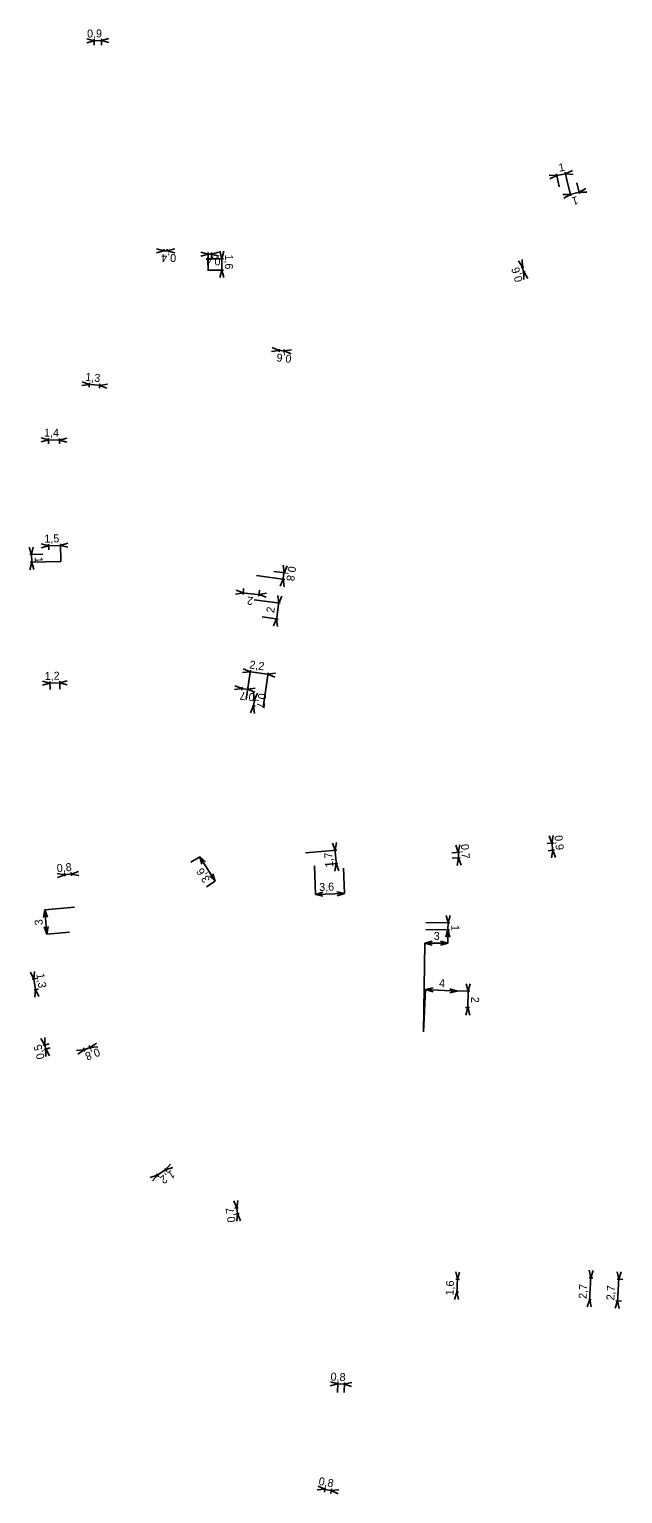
# Model space of a CAD drawing. Extents: x -732085 to -731961, y -1048713 to -1047966.
# Drawn here: x -732046.4 to -731972.2, y -1048148.7 to -1047965.8 of the extents above; entities that cross this region are included whole.
import ezdxf

# ---------------------------------------------------------------- set-up
doc = ezdxf.new("R2010")
doc.units = 0
doc.layers.add('Kota_NN', color=7, linetype='Continuous')
doc.layers.add('Kota_VN', color=7, linetype='Continuous')

msp = doc.modelspace()

# ---------------------------------------------------------------- linework, layer by layer
at = {"layer": 'Kota_NN'}
for p, q in [((-732038.27, -1047967.2), (-732039.2, -1047966.97)), ((-732038.27, -1047967.2), (-732039.19, -1047967.46)), ((-732038.47, -1047967.2), (-732037.17, -1047967.18)), ((-732038.26, -1047967.76), (-732038.27, -1047967)), ((-732037.37, -1047967.18), (-732036.45, -1047966.92)), ((-732037.36, -1047967.74), (-732037.37, -1047966.98)), ((-732037.37, -1047967.18), (-732036.44, -1047967.42)), ((-731980.45, -1047984.05), (-731981.41, -1047983.98)), ((-731980.45, -1047984.05), (-731981.32, -1047984.47)), ((-731980.65, -1047984.09), (-731979.16, -1047983.8)), ((-731980.18, -1047985.47), (-731980.49, -1047983.85)), ((-731979.2, -1047984.64), (-731979.4, -1047983.64)), ((-731979.36, -1047983.84), (-731978.49, -1047983.42)), ((-731979.36, -1047983.84), (-731978.4, -1047983.91)), ((-731979.2, -1047984.64), (-731978.69, -1047986.6)), ((-731977.49, -1047986.07), (-731978.94, -1047986.45)), ((-731977.98, -1047984.96), (-731977.63, -1047986.32)), ((-731977.68, -1047986.12), (-731976.84, -1047985.65)), ((-731977.68, -1047986.12), (-731976.72, -1047986.13)), ((-731978.74, -1047986.4), (-731979.7, -1047986.4)), ((-731978.74, -1047986.4), (-731979.58, -1047986.88)), ((-732029.57, -1047993.44), (-732030.5, -1047993.19)), ((-732029.57, -1047993.44), (-732030.5, -1047993.69)), ((-732028.94, -1047993.44), (-732029.77, -1047993.44)), ((-732029.57, -1047993.54), (-732029.57, -1047993.24)), ((-732029.14, -1047993.44), (-732028.21, -1047993.19)), ((-732029.14, -1047993.54), (-732029.14, -1047993.24)), ((-732029.14, -1047993.44), (-732028.21, -1047993.69)), ((-732022.32, -1047994.44), (-732022.57, -1047993.51)), ((-732022.32, -1047994.44), (-732022.07, -1047993.51)), ((-732024.03, -1047993.87), (-732024.96, -1047993.62)), ((-732024.03, -1047993.87), (-732024.96, -1047994.12)), ((-732024.26, -1047994.44), (-732022.12, -1047994.44)), ((-732023.43, -1047993.87), (-732024.23, -1047993.87)), ((-732024.03, -1047995.96), (-732024.03, -1047993.67)), ((-732023.63, -1047993.87), (-732022.7, -1047993.63)), ((-732023.63, -1047994.39), (-732023.63, -1047993.67)), ((-732023.63, -1047993.87), (-732022.7, -1047994.12)), ((-732022.32, -1047994.24), (-732022.32, -1047996.06)), ((-731984.77, -1047995.51), (-731985.27, -1047994.69)), ((-731984.55, -1047996.26), (-731984.83, -1047995.32)), ((-731984.77, -1047995.51), (-731984.79, -1047994.55)), ((-732024.05, -1047995.86), (-732022.12, -1047995.86)), ((-732022.32, -1047995.86), (-732022.57, -1047996.79)), ((-732022.32, -1047995.86), (-732022.07, -1047996.79)), ((-731984.91, -1047995.55), (-731984.58, -1047995.45)), ((-731984.74, -1047996.11), (-731984.41, -1047996.02)), ((-731984.6, -1047996.07), (-731984.1, -1047996.89)), ((-731984.6, -1047996.07), (-731984.58, -1047997.03)), ((-732015.15, -1048005.89), (-732016.1, -1048006.03)), ((-732015.15, -1048005.89), (-732016.04, -1048005.54)), ((-732014.35, -1048005.98), (-732015.34, -1048005.87)), ((-732015.13, -1048005.72), (-732015.17, -1048006.09)), ((-732014.53, -1048005.79), (-732014.57, -1048006.16)), ((-732014.55, -1048005.96), (-732013.6, -1048005.81)), ((-732014.55, -1048005.96), (-732013.66, -1048006.31)), ((-732038.87, -1048010.14), (-732039.77, -1048009.8)), ((-732038.91, -1048010.49), (-732038.85, -1048009.94)), ((-732038.87, -1048010.14), (-732039.82, -1048010.29)), ((-732039.07, -1048010.12), (-732037.37, -1048010.29)), ((-732037.6, -1048010.62), (-732037.55, -1048010.07)), ((-732037.57, -1048010.27), (-732036.62, -1048010.11)), ((-732037.57, -1048010.27), (-732036.67, -1048010.61)), ((-732043.98, -1048017.07), (-732044.91, -1048016.82)), ((-732043.98, -1048017.07), (-732044.91, -1048017.31)), ((-732044.18, -1048017.07), (-732042.41, -1048017.09)), ((-732043.99, -1048017.55), (-732043.98, -1048016.87)), ((-732042.61, -1048017.09), (-732041.68, -1048016.84)), ((-732042.61, -1048017.56), (-732042.61, -1048016.89)), ((-732042.61, -1048017.09), (-732041.68, -1048017.34)), ((-732043.96, -1048030.31), (-732044.89, -1048030.08)), ((-732043.94, -1048030.83), (-732043.96, -1048030.11)), ((-732042.44, -1048032.25), (-732042.5, -1048030.07)), ((-732042.49, -1048030.27), (-732041.57, -1048029.99)), ((-732046.11, -1048031.4), (-732046.38, -1048030.48)), ((-732044.68, -1048031.36), (-732046.31, -1048031.41)), ((-732046.11, -1048031.4), (-732045.88, -1048030.47)), ((-732046.11, -1048031.2), (-732046.07, -1048032.56)), ((-732043.96, -1048030.31), (-732044.88, -1048030.58)), ((-732044.16, -1048030.31), (-732042.29, -1048030.26)), ((-732042.49, -1048030.27), (-732041.56, -1048030.49)), ((-732046.08, -1048032.35), (-732046.3, -1048033.29)), ((-732042.44, -1048032.25), (-732046.28, -1048032.36)), ((-732046.08, -1048032.35), (-732045.81, -1048033.28)), ((-732015.83, -1048033.5), (-732014.35, -1048033.7)), ((-732014.52, -1048033.48), (-732014.68, -1048034.67)), ((-732014.55, -1048033.67), (-732014.66, -1048032.72)), ((-732014.55, -1048033.67), (-732014.17, -1048032.79)), ((-732017.97, -1048034.02), (-732014.46, -1048034.5)), ((-732014.65, -1048034.47), (-732015.03, -1048035.36)), ((-732014.65, -1048034.47), (-732014.53, -1048035.43)), ((-732019.66, -1048036.2), (-732020.6, -1048036.36)), ((-732019.66, -1048036.2), (-732020.55, -1048035.86)), ((-732017.46, -1048036.42), (-732019.85, -1048036.18)), ((-732019.6, -1048035.65), (-732019.67, -1048036.4)), ((-732018.27, -1048037.05), (-732015.02, -1048037.49)), ((-732017.61, -1048035.85), (-732017.68, -1048036.59)), ((-732017.66, -1048036.4), (-732016.72, -1048036.24)), ((-732017.66, -1048036.4), (-732016.76, -1048036.73)), ((-732015.51, -1048039.64), (-732015.19, -1048037.27)), ((-732015.21, -1048037.47), (-732015.33, -1048036.51)), ((-732015.21, -1048037.47), (-732014.84, -1048036.58)), ((-732017.27, -1048039.19), (-732015.29, -1048039.46)), ((-732015.48, -1048039.44), (-732015.86, -1048040.32)), ((-732015.48, -1048039.44), (-732015.37, -1048040.39)), ((-732018.77, -1048046.04), (-732019.72, -1048046.15)), ((-732018.77, -1048046.04), (-732019.65, -1048045.66)), ((-732019.27, -1048049.49), (-732018.74, -1048045.84)), ((-732018.97, -1048046.01), (-732016.37, -1048046.38)), ((-732017.16, -1048050.49), (-732016.54, -1048046.16)), ((-732016.57, -1048046.35), (-732015.61, -1048046.24)), ((-732016.57, -1048046.35), (-732015.68, -1048046.73)), ((-732043.8, -1048047.45), (-732044.73, -1048047.22)), ((-732043.8, -1048047.45), (-732044.72, -1048047.72)), ((-732044, -1048047.46), (-732042.38, -1048047.42)), ((-732043.78, -1048048.25), (-732043.8, -1048047.25)), ((-732042.58, -1048047.43), (-732041.66, -1048047.16)), ((-732042.56, -1048048.21), (-732042.58, -1048047.23)), ((-732042.58, -1048047.43), (-732041.65, -1048047.66)), ((-732019.79, -1048048.15), (-732020.74, -1048048.28)), ((-732019.79, -1048048.15), (-732020.68, -1048047.79)), ((-732018.9, -1048048.26), (-732019.99, -1048048.13)), ((-732019.81, -1048048.34), (-732019.77, -1048047.95)), ((-732019.12, -1048048.42), (-732019.07, -1048048.04)), ((-732019.09, -1048048.23), (-732018.14, -1048048.1)), ((-732019.09, -1048048.23), (-732018.2, -1048048.59)), ((-732018.07, -1048049.62), (-732018.45, -1048049.56)), ((-732018.23, -1048049.39), (-732018.38, -1048050.51)), ((-732018.26, -1048049.59), (-732018.37, -1048048.64)), ((-732018.26, -1048049.59), (-732017.88, -1048048.71)), ((-732018.35, -1048050.31), (-732018.73, -1048051.19)), ((-732018.17, -1048050.34), (-732018.55, -1048050.28)), ((-732018.35, -1048050.31), (-732018.24, -1048051.26)), ((-731981.07, -1048067.44), (-731981.41, -1048066.54)), ((-731981.07, -1048067.44), (-731980.92, -1048066.49)), ((-732011.85, -1048068.65), (-732007.97, -1048068.32)), ((-732008.17, -1048068.34), (-732008.49, -1048067.44)), ((-732008.01, -1048070.21), (-732008.19, -1048068.14)), ((-732008.17, -1048068.34), (-732008, -1048067.39)), ((-731992.78, -1048068.6), (-731993.09, -1048067.69)), ((-731992.8, -1048068.4), (-731992.72, -1048069.5)), ((-731992.78, -1048068.6), (-731992.6, -1048067.66)), ((-731981.65, -1048067.5), (-731980.87, -1048067.42)), ((-731981.55, -1048068.4), (-731980.77, -1048068.31)), ((-731980.97, -1048068.33), (-731981.12, -1048069.28)), ((-731981.09, -1048067.24), (-731980.95, -1048068.53)), ((-731980.97, -1048068.33), (-731980.62, -1048069.23)), ((-732026.19, -1048069.85), (-732025.09, -1048069.15)), ((-732023.15, -1048072.2), (-732025.09, -1048069.15)), ((-732025.09, -1048069.15), (-732024.38, -1048069.8)), ((-732025.09, -1048069.15), (-732024.8, -1048070.07)), ((-732010.73, -1048070.29), (-732010.62, -1048073.86)), ((-732009.38, -1048070.12), (-732007.83, -1048069.99)), ((-732008.03, -1048070.01), (-732008.2, -1048070.95)), ((-732008.03, -1048070.01), (-732007.7, -1048070.91)), ((-731993.58, -1048068.65), (-731992.58, -1048068.59)), ((-731993.53, -1048069.35), (-731992.54, -1048069.28)), ((-731992.74, -1048069.3), (-731992.92, -1048070.24)), ((-731992.74, -1048069.3), (-731992.43, -1048070.21)), ((-732041.95, -1048071.4), (-732042.89, -1048071.24)), ((-732041.95, -1048071.4), (-732042.85, -1048071.73)), ((-732042.15, -1048071.42), (-732040.94, -1048071.31)), ((-732041.93, -1048071.6), (-732041.96, -1048071.2)), ((-732041.12, -1048071.53), (-732041.16, -1048071.13)), ((-732041.14, -1048071.33), (-732040.24, -1048071)), ((-732041.14, -1048071.33), (-732040.19, -1048071.49)), ((-732024.25, -1048072.9), (-732023.15, -1048072.2)), ((-732023.15, -1048072.2), (-732023.86, -1048071.55)), ((-732023.15, -1048072.2), (-732023.44, -1048071.28)), ((-732007.1, -1048070.57), (-732006.99, -1048073.74)), ((-732010.62, -1048073.86), (-732009.7, -1048073.58)), ((-732010.62, -1048073.86), (-732006.99, -1048073.74)), ((-732010.62, -1048073.86), (-732009.68, -1048074.08)), ((-732006.99, -1048073.74), (-732007.93, -1048073.52)), ((-732006.99, -1048073.74), (-732007.91, -1048074.02)), ((-732044.45, -1048075.8), (-732044.62, -1048076.74)), ((-732040.75, -1048075.46), (-732044.45, -1048075.8)), ((-732044.18, -1048078.82), (-732044.45, -1048075.8)), ((-732044.45, -1048075.8), (-732044.12, -1048076.7)), ((-731996.81, -1048077.37), (-731993.85, -1048077.41)), ((-731994.05, -1048077.41), (-731994.29, -1048076.48)), ((-731994.05, -1048077.21), (-731994.07, -1048078.46)), ((-731994.05, -1048077.41), (-731993.79, -1048076.48)), ((-732044.18, -1048078.82), (-732044.51, -1048077.92)), ((-732044.18, -1048078.82), (-732044.01, -1048077.88)), ((-732041.37, -1048078.57), (-732044.18, -1048078.82)), ((-731996.81, -1048078.23), (-731993.86, -1048078.27)), ((-731994.06, -1048078.26), (-731994.32, -1048079.19)), ((-731994.05, -1048078.22), (-731994.08, -1048079.97)), ((-731994.06, -1048078.26), (-731993.83, -1048079.19)), ((-731997.1, -1048091.03), (-731996.96, -1048079.94)), ((-731996.96, -1048079.94), (-731996.03, -1048079.7)), ((-731996.96, -1048079.94), (-731994.08, -1048079.97)), ((-731996.96, -1048079.94), (-731996.03, -1048080.2)), ((-731994.08, -1048079.97), (-731995.01, -1048080.21)), ((-731994.08, -1048079.97), (-731995, -1048079.71)), ((-732045.81, -1048084.44), (-732046.21, -1048083.56)), ((-732045.46, -1048084.38), (-732046.01, -1048084.47)), ((-732045.84, -1048084.24), (-732045.56, -1048085.94)), ((-732045.81, -1048084.44), (-732045.72, -1048083.48)), ((-731991.54, -1048085.95), (-731991.77, -1048085.02)), ((-731991.54, -1048085.95), (-731991.27, -1048085.03)), ((-732045.24, -1048085.69), (-732045.79, -1048085.78)), ((-732045.59, -1048085.75), (-732045.69, -1048086.7)), ((-732045.59, -1048085.75), (-732045.2, -1048086.62)), ((-731997.1, -1048091.03), (-731996.85, -1048085.75)), ((-731996.85, -1048085.75), (-731995.91, -1048085.55)), ((-731996.85, -1048085.75), (-731992.9, -1048085.94)), ((-731996.85, -1048085.75), (-731995.93, -1048086.05)), ((-731992.9, -1048085.94), (-731993.83, -1048086.15)), ((-731992.9, -1048085.94), (-731993.81, -1048085.65)), ((-731992.89, -1048085.86), (-731992.9, -1048085.94)), ((-731992.89, -1048085.92), (-731991.34, -1048085.96)), ((-731991.54, -1048085.75), (-731991.59, -1048088.2)), ((-731991.87, -1048088), (-731991.38, -1048088.01)), ((-731991.58, -1048088), (-731991.85, -1048088.93)), ((-731991.58, -1048088), (-731991.35, -1048088.94)), ((-732044.45, -1048092.69), (-732044.92, -1048091.86)), ((-732044.45, -1048092.69), (-732044.44, -1048091.73)), ((-732043.89, -1048092.55), (-732044.64, -1048092.74)), ((-732043.77, -1048093.03), (-732044.52, -1048093.22)), ((-732044.27, -1048093.37), (-732044.5, -1048092.5)), ((-732044.33, -1048093.17), (-732043.85, -1048094.01)), ((-732044.33, -1048093.17), (-732044.33, -1048094.13)), ((-732039.53, -1048093.28), (-732040.49, -1048093.37)), ((-732039.53, -1048093.28), (-732040.31, -1048093.84)), ((-732038.6, -1048092.92), (-732039.72, -1048093.35)), ((-732039.62, -1048093.03), (-732039.46, -1048093.46)), ((-732038.88, -1048092.75), (-732038.71, -1048093.18)), ((-732038.78, -1048092.99), (-732038, -1048092.43)), ((-732038.78, -1048092.99), (-732037.83, -1048092.9)), ((-732029.19, -1048108.16), (-732030.53, -1048109.04)), ((-732030.21, -1048109.15), (-732030.47, -1048108.76)), ((-732029.21, -1048108.49), (-732029.46, -1048108.1)), ((-732029.36, -1048108.27), (-732028.72, -1048107.55)), ((-732029.36, -1048108.27), (-732028.44, -1048107.97)), ((-732030.36, -1048108.93), (-732031.27, -1048109.23)), ((-732030.36, -1048108.93), (-732031, -1048109.64)), ((-732020.45, -1048113.05), (-732020.83, -1048112.16)), ((-732020.45, -1048113.05), (-732020.34, -1048112.09)), ((-732020.68, -1048113.08), (-732020.26, -1048113.02)), ((-732020.58, -1048113.78), (-732020.15, -1048113.72)), ((-732020.32, -1048113.94), (-732020.48, -1048112.85)), ((-732020.35, -1048113.74), (-732020.46, -1048114.7)), ((-732020.35, -1048113.74), (-732019.97, -1048114.63)), ((-731972.72, -1048121.95), (-731972.92, -1048121.01)), ((-731972.72, -1048121.95), (-731972.42, -1048121.03)), ((-731972.23, -1048121.97), (-731972.93, -1048121.94)), ((-731972.89, -1048124.84), (-731972.71, -1048121.75)), ((-731972.88, -1048124.64), (-731973.18, -1048125.55)), ((-731972.38, -1048124.67), (-731973.08, -1048124.63)), ((-731972.88, -1048124.64), (-731972.68, -1048125.58)), ((-732007.84, -1048135.03), (-732008.78, -1048135.25)), ((-732007.84, -1048135.03), (-732008.76, -1048134.75)), ((-732008.04, -1048135.03), (-732006.82, -1048135.07)), ((-732007.88, -1048136.08), (-732007.83, -1048134.83)), ((-732007.05, -1048136.11), (-732007.01, -1048134.86)), ((-732007.02, -1048135.06), (-732006.08, -1048134.85)), ((-732007.02, -1048135.06), (-732006.1, -1048135.35)), ((-732009.43, -1048148.19), (-732010.39, -1048148.27)), ((-732009.43, -1048148.19), (-732010.3, -1048147.78)), ((-732009.63, -1048148.16), (-732008.45, -1048148.37)), ((-732009.5, -1048148.56), (-732009.4, -1048147.99)), ((-732008.71, -1048148.7), (-732008.61, -1048148.13)), ((-732008.65, -1048148.33), (-732007.69, -1048148.25)), ((-732008.65, -1048148.33), (-732007.78, -1048148.74))]:
    msp.add_line(p, q, dxfattribs=at)
at = {"layer": 'Kota_VN'}
for p, q in [((-731992.89, -1048121.95), (-731993.1, -1048121.02)), ((-731992.89, -1048121.95), (-731992.61, -1048121.04)), ((-731976.21, -1048121.77), (-731976.41, -1048120.83)), ((-731976.37, -1048124.67), (-731976.2, -1048121.57)), ((-731976.21, -1048121.77), (-731975.92, -1048120.85)), ((-731992.62, -1048121.96), (-731993.09, -1048121.95)), ((-731992.96, -1048123.76), (-731992.88, -1048121.75)), ((-731975.98, -1048121.78), (-731976.41, -1048121.76)), ((-731992.95, -1048123.56), (-731993.24, -1048124.47)), ((-731992.96, -1048123.56), (-731992.75, -1048123.56)), ((-731992.95, -1048123.56), (-731992.74, -1048124.49)), ((-731976.35, -1048124.47), (-731976.65, -1048125.38)), ((-731976.36, -1048124.47), (-731976.16, -1048124.48)), ((-731976.35, -1048124.47), (-731976.16, -1048125.41))]:
    msp.add_line(p, q, dxfattribs=at)

# ---------------------------------------------------------------- texts
at = {"layer": 'Kota_NN'}
for s, rotation, p in [('0,9', 0.9636, (-732039.15, -1047966.81)), ('1', 10.8499, (-731980.14, -1047983.58)), ('1', 194.7604, (-731977.95, -1047986.61)), ('0,4', 180, (-732028.03, -1047993.84)), ('0,4', 180, (-732022.5, -1047994.27)), ('1,6', 270, (-732021.92, -1047993.91)), ('0,6', 106.5338, (-731984.69, -1047997.18)), ('0,6', 173.6524, (-732013.57, -1048006.47)), ('1,3', 354.343, (-732039.41, -1048009.68)), ('1,4', 359.5477, (-732044.53, -1048016.67)), ('1,5', 1.5502, (-732044.48, -1048029.92)), ('1', 271.6009, (-732045.7, -1048031.7)), ('0,8', 262.206, (-732014.02, -1048032.81)), ('2', 174.3664, (-732018.37, -1048036.73)), ('2', 82.1809, (-732015.79, -1048038.73)), ('2,2', 351.7745, (-732018.93, -1048045.61)), ('1,2', 1.2217, (-732044.44, -1048047.07)), ('0,7', 173.1394, (-732018.17, -1048048.75)), ('0,7', 262.1422, (-732017.73, -1048048.69)), ('0,9', 276.1214, (-731980.76, -1048066.52)), ('0,7', 273.7502, (-731992.45, -1048067.6)), ('0,8', 5.1705, (-732042.9, -1048071.09)), ('1,7', 94.8529, (-732008.39, -1048070.44)), ('3,6', 122.5197, (-732023.74, -1048072.01)), ('3,6', 1.8966, (-732010.14, -1048073.44)), ('3', 95.1283, (-732044.68, -1048077.68)), ('3', 359.2701, (-731995.85, -1048079.55)), ('1', 269.2663, (-731993.65, -1048077.67)), ('1,3', 279.4703, (-732045.51, -1048083.8)), ('4', 357.2739, (-731995.19, -1048085.43)), ('2', 268.8653, (-731991.16, -1048086.65)), ('0,5', 104.6446, (-732044.44, -1048094.32)), ('0,8', 200.6899, (-732037.77, -1048093.04)), ('1,2', 213.316, (-732028.6, -1048108.25)), ('0,7', 98.4615, (-732020.6, -1048114.77)), ('2,7', 86.7542, (-731973.28, -1048124.6)), ('0,8', 357.9127, (-732008.74, -1048134.6)), ('0,8', 349.8627, (-732010.28, -1048147.63))]:
    msp.add_text(s, height=1, rotation=rotation, dxfattribs=at).set_placement(p)
at = {"layer": 'Kota_VN'}
for s, rotation, p in [('1,6', 87.7591, (-731993.37, -1048123.98)), ('2,7', 87.0069, (-731976.75, -1048124.42))]:
    msp.add_text(s, height=1, rotation=rotation, dxfattribs=at).set_placement(p)

doc.saveas('drawing.dxf')
